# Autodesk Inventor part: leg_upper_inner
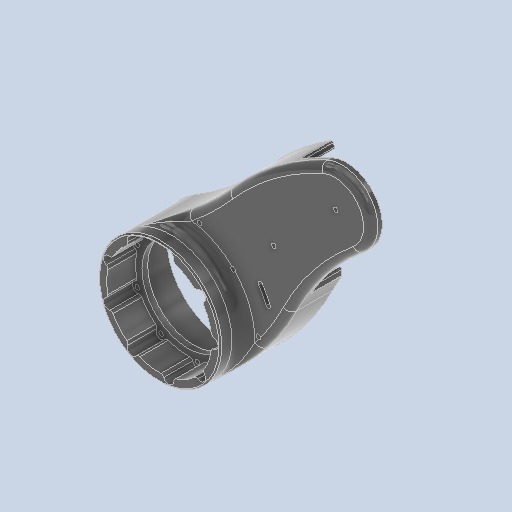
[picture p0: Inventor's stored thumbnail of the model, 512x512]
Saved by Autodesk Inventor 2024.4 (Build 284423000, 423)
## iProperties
Created: 2026-01
Part Number: leg_upper_inner
Material: Generic
Document SubType Name: Modeling
Designer: AdminForWorker
Density: 1 g/cm^3
Appearance: Default
Title: leg_upper_inner
Author: AdminForWorker
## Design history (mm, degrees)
feature "Body2"
body "Solid1"
